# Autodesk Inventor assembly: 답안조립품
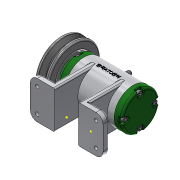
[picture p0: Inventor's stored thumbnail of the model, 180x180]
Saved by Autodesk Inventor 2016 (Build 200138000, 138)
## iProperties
Created: 2017-02
Part Number: 답안조립품
Material: 일반
Document SubType Name: Assembly
Designer: H
Author: H
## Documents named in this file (16)
- C:\Users\CAMTIC\Desktop\470207V1018\답안조립품.iam
- C:\Users\CAMTIC\Desktop\470207V1018\470207V1018.ipt
- C:\Users\CAMTIC\Desktop\470207V1018\V벨트풀리.ipt
- C:\Users\CAMTIC\Desktop\470207V1018\너트 M 8.ipt
- C:\Users\CAMTIC\Desktop\470207V1018\니플 M 6 x 0.75.ipt
- C:\Users\CAMTIC\Desktop\470207V1018\뒤커버.ipt
- C:\Users\CAMTIC\Desktop\470207V1018\베어링 15 x 32 x 9.ipt
- C:\Users\CAMTIC\Desktop\470207V1018\볼트 M 6 x 8.ipt
- C:\Users\CAMTIC\Desktop\470207V1018\볼트 M4 x 12.ipt
- C:\Users\CAMTIC\Desktop\470207V1018\스프링와셔 8.ipt
- C:\Users\CAMTIC\Desktop\470207V1018\앞커버.ipt
- C:\Users\CAMTIC\Desktop\470207V1018\오일 실 15 25 7.ipt
- C:\Users\CAMTIC\Desktop\470207V1018\와셔 6x11.5.ipt
- C:\Users\CAMTIC\Desktop\470207V1018\와셔 8x17.ipt
- C:\Users\CAMTIC\Desktop\470207V1018\축.ipt
- C:\Users\CAMTIC\Desktop\470207V1018\키 3 x 3 x 12.ipt
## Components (12 placed, 4 different names)
1. 470207V1018:1
2. V벨트풀리:1
3. KS B 2023 6002 - 15 x 32 x 9:1
4. KS B 2023 6002 - 15 x 32 x 9:2
5. ISO 4762 M4 x 12:1
6. ISO 4762 M4 x 12:3
7. ISO 4762 M4 x 12:4
8. ISO 4762 M4 x 12:5
9. ISO 4762 M4 x 12:2
10. ISO 4762 M4 x 12:6
11. ISO 4762 M4 x 12:7
12. ISO 4762 M4 x 12:8
